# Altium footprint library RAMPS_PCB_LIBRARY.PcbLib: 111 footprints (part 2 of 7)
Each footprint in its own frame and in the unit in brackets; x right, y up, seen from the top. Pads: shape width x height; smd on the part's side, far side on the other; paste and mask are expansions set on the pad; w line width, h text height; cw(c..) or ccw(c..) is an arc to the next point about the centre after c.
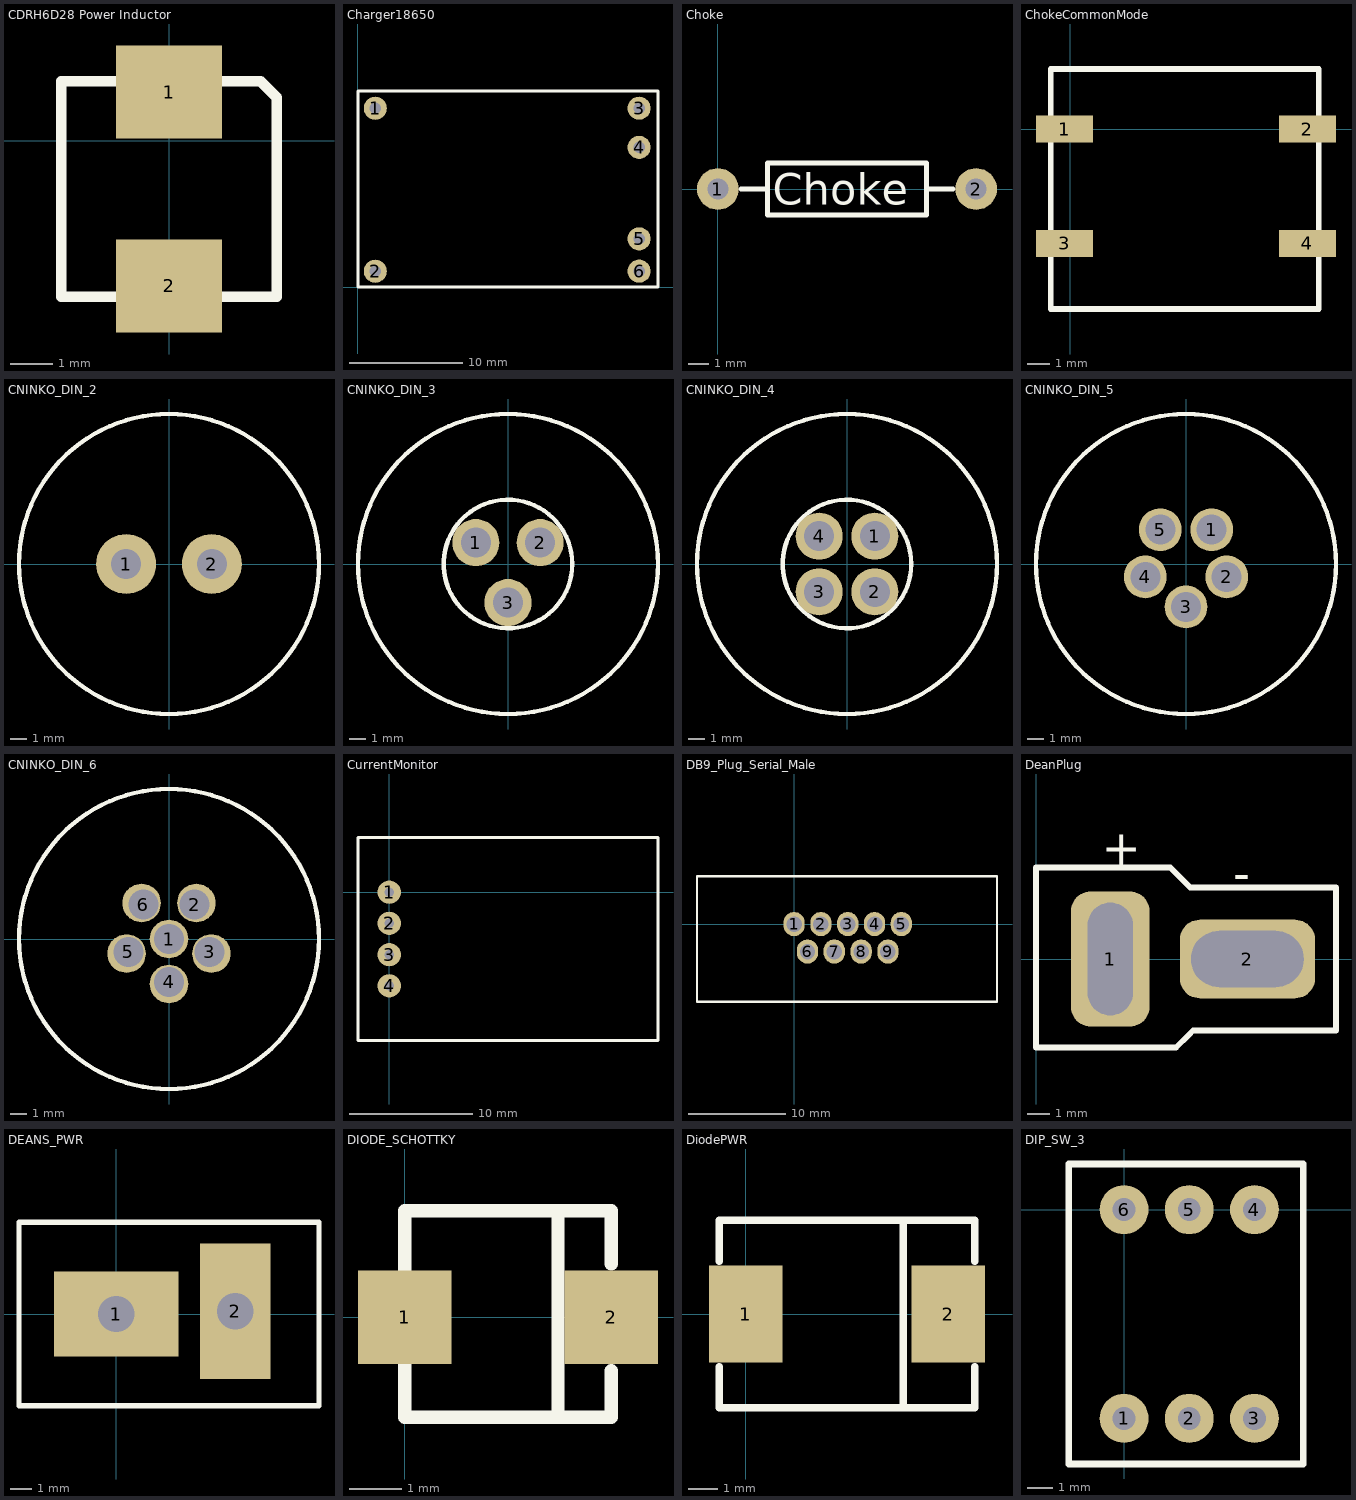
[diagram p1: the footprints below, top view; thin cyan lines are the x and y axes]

## CDRH6D28 Power Inductor [mm]
pads (2):
  rect 2.5x2.2 smd: 1(0,1.143) 2(0,-3.429)
Top Overlay:
  lines w0.254: -2.54,-3.683 2.54,-3.683 2.54,1.016 2.159,1.397 -2.54,1.397 -2.54,-3.302 -2.54,-3.683

## Charger18650 [mil]
pads (6):
  round 80 hole 40: 1(60,620) 2(60,55) 3(974.41,620.08) 4(974.41,484.25) 5(974.41,167.32) 6(974.41,55.12)
Top Overlay:
  lines w10: 0,0 0,680 1040,680 1040,0 0,0

## Choke [mil]
pads (2):
  round 80 hole 40: 1(0,0) 2(495,0)
Top Overlay:
  lines w10: 45,0 95,0 ; 400,0 450,0 ; 95,0 95,50 400,50 400,-50 95,-50 95,0
  text "Choke" at 105,-30 h60

## ChokeCommonMode [mil]
pads (4):
  rect 100x47.24 smd: 1(-10,0) 2(415,0) 3(-10,-200) 4(415,-200)
Top Overlay:
  lines w10: -34.27,104.27 -34.27,-315 435,-315 435,105 -34.27,105

## CNINKO_DIN_2 [mil]
pads (2):
  round 140 hole 70: 1(-100,0) 2(100,0)
Top Overlay:
  circle w10: c0,0 r350

## CNINKO_DIN_3 [mil]
pads (3):
  round 110 hole 70: 1(-75,50) 2(75,50) 3(0,-90)
Top Overlay:
  circle w10: c0,0 r150.08
  circle w10: c0,0 r350

## CNINKO_DIN_4 [mil]
pads (4):
  round 110 hole 70: 1(65,65) 2(65,-65) 3(-65,-65) 4(-65,65)
Top Overlay:
  circle w10: c0,0 r350
  circle w10: c0,0 r150.08

## CNINKO_DIN_5 [mil]
pads (5):
  round 100 hole 70: 1(60,80) 2(95,-30) 3(0,-100) 4(-95,-30) 5(-60,80)
Top Overlay:
  circle w10: c0,0 r350

## CNINKO_DIN_6 [mil]
pads (6):
  round 90 hole 70: 1(0,0)
  round 90 hole 70 copper offset 4,4: 2(60,80)
  round 90 hole 70 copper offset 4,-4: 3(95,-30)
  round 90 hole 70 copper offset 0,-5: 4(0,-100)
  round 90 hole 70 copper offset -4,-4: 5(-95,-30)
  round 90 hole 70 copper offset -4,4: 6(-60,80)
Top Overlay:
  circle w10: c0,0 r350

## CurrentMonitor [mil]
pads (4):
  round 75 hole 30: 1(0,0) 2(0,-100) 3(0,-200) 4(0,-300)
Top Overlay:
  lines w10: -100,-475 -100,175 860,175 860,-475 -100,-475

## DB9_Plug_Serial_Male [mm]
pads (9):
  oval 2.2x2.5 hole 1.6: 1(0,0) 2(2.77,0) 3(5.54,0) 4(8.31,0) 5(11.08,0) 6(1.385,-2.84) 7(4.155,-2.84) 8(6.925,-2.84) 9(9.695,-2.84)
Top Overlay:
  lines w0.254: -10.033,-8.047 20.967,-8.047 20.967,4.953 -10.033,4.953 -10.033,-8.047

## DeanPlug [mm]
pads (2):
  rrect50% 3.5x6 hole 2 slot 5 at 90 deg: 1(3.302,0)
  rrect50% 6x3.5 hole 2.5 slot 5 at 0 deg: 2(9.398,0)
Top Overlay:
  lines w0.254: 0,-3.937 1.651,-3.937 6.223,-3.937 6.794,-3.365 6.985,-3.175 13.335,-3.175 13.335,3.175 6.858,3.175 5.969,4.064 1.524,4.064 0,4.064 0,-3.937
  text "+" at 2.921,4.191 h1.52
  text "-" at 8.763,3.048 h1.52

## DEANS_PWR [mil]
pads (2):
  rect 230x157.48 hole 66.93 square: 1(0,0)
  rect 130x250 hole 66.93 square: 2(220,5)
Top Overlay:
  lines w10: -180,-170 375,-170 375,0 375,170 -180,170 -180,-170

## DIODE_SCHOTTKY [mil]
pads (2):
  rect 70x70 smd: 1(0,0) 2(155,0)
Top Overlay:
  lines w10: 0,-35 0,-75 155,-75 155,-40 ; 0,35 0,80 155,80 155,40 ; 115,-70 115,80

## DiodePWR [mm]
pads (2):
  rect 2.5x3.3 smd: 1(0,0) 2(6.858,0)
Top Overlay:
  lines w0.254: -0.889,-1.778 -0.889,-3.175 7.747,-3.175 7.747,-1.778 ; -0.889,1.778 -0.889,3.175 7.747,3.175 7.747,1.778 ; 5.334,-3.175 5.334,3.048

## DIP_SW_3 [mil]
pads (6):
  round 75 hole 35: 1(0,-320) 2(100,-320) 3(200,-320) 4(200,0) 5(100,0) 6(0,0)
Top Overlay:
  lines w10: -85,-390 -85,70 275,70 275,-390 -85,-390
